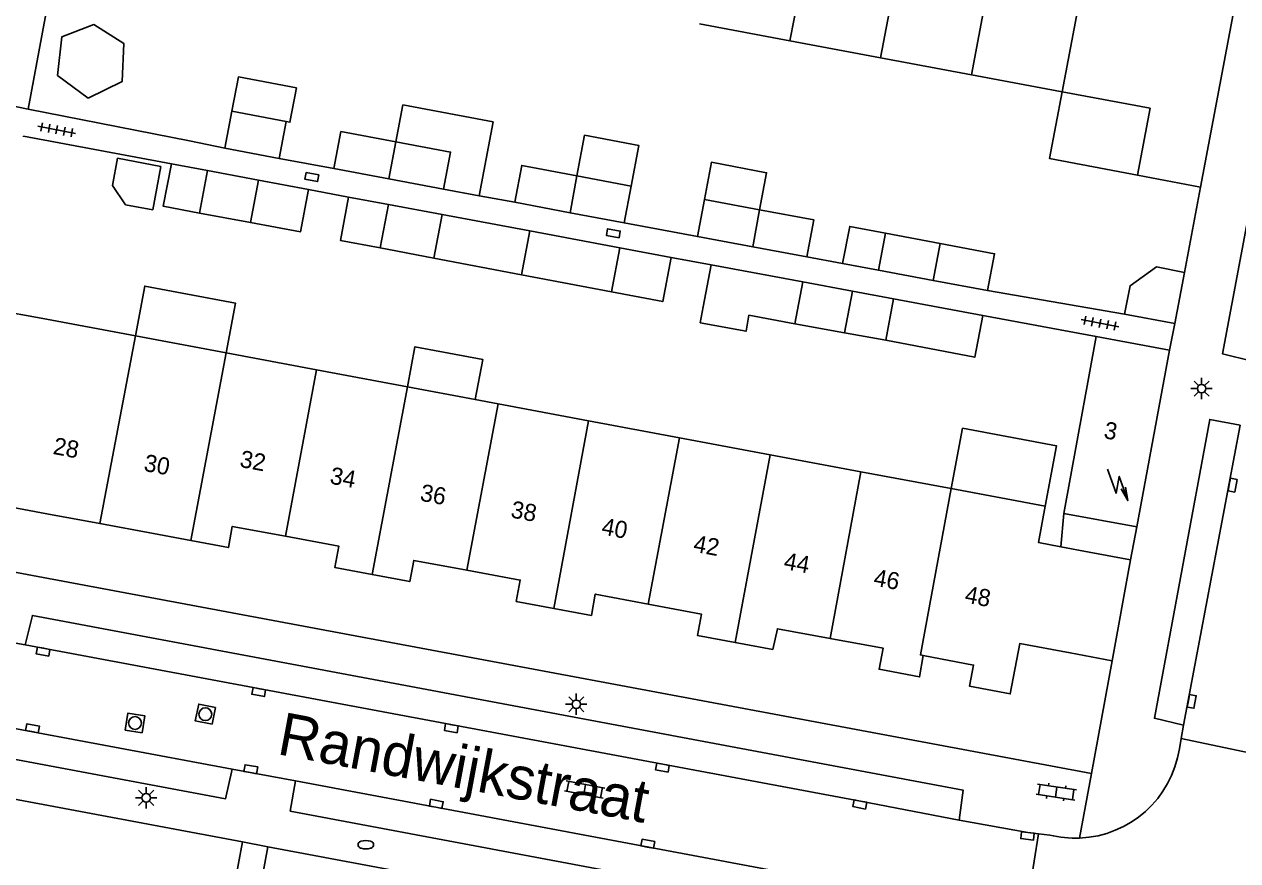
# Model space of a CAD drawing. Extents: x 124000 to 128010, y 398999 to 403000.
# Drawn here: x 126626.3 to 126697.3, y 399664.9 to 399713.9 of the extents above; entities that cross this region are included whole.
import ezdxf

# ---------------------------------------------------------------- set-up
doc = ezdxf.new("R2010")
doc.units = 0
for name, color, linetype in [('gg-afsc-erfafscheiding', 7, 'Continuous'), ('gg-afsc-muur', 7, 'Continuous'), ('gg-anno-huisnummerreeks BGT', 7, 'Continuous'), ('gg-anno-openbare ruimte label', 7, 'Continuous'), ('gg-bbg-bijgebouw', 7, 'Continuous'), ('gg-bbg-gedigitaliseerde bijgebouw', 7, 'Continuous'), ('gg-bbg-hoofdgebouw', 7, 'Continuous'), ('gg-bbg-luifel en loopbrug', 7, 'Continuous'), ('gg-bbg-tussenscheiding', 7, 'Continuous'), ('gg-knt-verharding', 7, 'Continuous'), ('gg-knt-verharding nz', 7, 'Continuous'), ('gt-grn-weggrens', 7, 'Continuous'), ('gt-symb-brandkraan', 7, 'Continuous'), ('gt-symb-klinker verharding', 7, 'Continuous'), ('gt-symb-kolk', 7, 'Continuous'), ('gt-symb-kolk center center', 7, 'Continuous'), ('gt-symb-lichtmast', 7, 'Continuous'), ('gt-symb-rioolschacht', 7, 'Continuous'), ('gt-symb-tegel verharding', 7, 'Continuous'), ('gt-symb-trafo symbool', 7, 'Continuous')]:
    doc.layers.add(name, color=color, linetype=linetype)

# ---------------------------------------------------------------- blocks, each defined once
blk = doc.blocks.new('gt0-LMAST')
at = {"layer": 'gt-symb-lichtmast'}
for p, q in [((-0.182, 0.173), (-0.447, 0.438)), ((-0.005, 0.246), (-0.005, 0.621)), ((0.172, 0.173), (0.437, 0.438)), ((-0.255, -0.004), (-0.63, -0.004)), ((-0.182, -0.181), (-0.447, -0.446)), ((-0.005, -0.254), (-0.005, -0.629)), ((0.437, -0.446), (0.172, -0.181)), ((0.245, -0.004), (0.62, -0.004))]:
    blk.add_line(p, q, dxfattribs=at)
blk.add_circle((-0.005, -0.004), 0.25, dxfattribs=at)
blk = doc.blocks.new('gt0-KOLK')
at = {"layer": 'gt-symb-kolk'}
blk.add_lwpolyline([(0, 0), (0.375, 0), (0.375, 0.4), (-0.375, 0.4), (-0.375, 0), (0, 0)], dxfattribs=at)
blk = doc.blocks.new('gt0-TEG1')
at = {"layer": 'gt-symb-tegel verharding'}
for p, q in [((-1.125, 0), (1.125, 0)), ((-0.9, -0.25), (-0.9, 0.25)), ((-0.45, -0.25), (-0.45, 0.25)), ((0, -0.25), (0, 0.25)), ((0.45, -0.25), (0.45, 0.25)), ((0.9, -0.25), (0.9, 0.25))]:
    blk.add_line(p, q, dxfattribs=at)
blk = doc.blocks.new('gt0-HSP')
at = {"layer": 'gt-symb-trafo symbool'}
for points in [[(0.771, 0.746), (-0.529, -0.004), (0.471, -0.004), (-0.829, -0.754)], [(-0.217, -0.24), (-0.829, -0.754), (-0.077, -0.48)]]:
    blk.add_lwpolyline(points, dxfattribs=at)
blk = doc.blocks.new('gt0-KL1')
at = {"layer": 'gt-symb-klinker verharding'}
for p, q in [((-1.15, 0.3), (1.15, 0.3)), ((-1, -0.3), (-1, 0.3)), ((-0.5, 0.3), (-0.5, 0.45)), ((0, -0.3), (0, 0.3)), ((0.5, 0.3), (0.5, 0.45)), ((1, -0.3), (1, 0.3)), ((-1.15, -0.3), (1.15, -0.3)), ((-0.5, -0.45), (-0.5, -0.3)), ((0.5, -0.45), (0.5, -0.3))]:
    blk.add_line(p, q, dxfattribs=at)
blk = doc.blocks.new('gt0-KOLKCC')
at = {"layer": 'gt-symb-kolk center center'}
blk.add_lwpolyline([(-0.375, 0.2), (0.375, 0.2), (0.375, -0.2), (-0.375, -0.2)], close=True, dxfattribs=at)
blk = doc.blocks.new('gt0-BR')
at = {"layer": 'gt-symb-brandkraan'}
for centre, radius, start, end in [((-0.244, 0), 0.206, 107.56694, 252.43307), ((0.599, -2.664), 3, 106.89205, 107.56694), ((0, -0.691), 0.938, 73.10799, 106.89205), ((-0.599, -2.664), 3, 72.43309, 73.10799), ((0.244, 0), 0.206, 287.56695, 72.43309), ((0.599, 2.664), 3, 252.43307, 253.10797), ((0, 0.691), 0.938, 253.10797, 286.89206), ((-0.599, 2.664), 3, 286.89206, 287.56695)]:
    blk.add_arc(centre, radius, start, end, dxfattribs=at)
blk = doc.blocks.new('gt0-RS')
at = {"layer": 'gt-symb-rioolschacht'}
blk.add_lwpolyline([(-0.5, -0.5), (0.5, -0.5), (0.5, 0.5), (-0.5, 0.5)], close=True, dxfattribs=at)
blk.add_circle((0, 0), 0.375, dxfattribs=at)

msp = doc.modelspace()

# ---------------------------------------------------------------- linework, layer by layer
at = {"layer": 'gg-afsc-erfafscheiding'}
for p, q in [((126644.385, 399705.421), (126641.192, 399706.016)), ((126642.904, 399704.195), (126645.241, 399703.758)), ((126654.976, 399703.446), (126652.89, 399703.835)), ((126665.666, 399701.453), (126661.384, 399702.239)), ((126664.132, 399700.225), (126666.47, 399699.788)), ((126674.168, 399699.868), (126672.079, 399700.257)), ((126690.669, 399696.893), (126682.654, 399698.281)), ((126689.014, 399695.59), (126682.364, 399696.815))]:
    msp.add_line(p, q, dxfattribs=at)
for points in [[(126626.495, 399708.888), (126627.958, 399716.771), (126628.884, 399718.452), (126629.145, 399718.635)], [(126626.495, 399708.888), (126635.926, 399707.054), (126638.005, 399706.61)]]:
    msp.add_lwpolyline(points, dxfattribs=at)
at = {"layer": 'gg-afsc-muur'}
msp.add_line((126695.113, 399704.337), (126694.183, 399699.35), dxfattribs=at)
msp.add_lwpolyline([(126634.872, 399705.697), (126626.223, 399707.315), (126626.217, 399707.284)], dxfattribs=at)
at = {"layer": 'gg-bbg-bijgebouw'}
for p, q in [((126641.192, 399706.016), (126638.005, 399706.61)), ((126647.611, 399704.819), (126644.385, 399705.421)), ((126636.983, 399705.302), (126639.968, 399704.744)), ((126639.968, 399704.744), (126642.904, 399704.195)), ((126650.804, 399704.224), (126647.611, 399704.819)), ((126647.577, 399703.321), (126650.727, 399702.732)), ((126658.209, 399702.837), (126654.976, 399703.446)), ((126650.727, 399702.732), (126655.855, 399701.773)), ((126661.384, 399702.239), (126658.209, 399702.837)), ((126655.855, 399701.773), (126661.129, 399700.787)), ((126665.666, 399701.453), (126668.9, 399700.85)), ((126661.129, 399700.787), (126664.132, 399700.225)), ((126668.9, 399700.85), (126672.079, 399700.257)), ((126666.47, 399699.788), (126671.827, 399698.786)), ((126679.475, 399698.876), (126676.257, 399699.479)), ((126693.613, 399696.35), (126694.183, 399699.35)), ((126671.827, 399698.786), (126674.737, 399698.242)), ((126682.654, 399698.281), (126679.475, 399698.876)), ((126677.145, 399697.791), (126682.364, 399696.815)), ((126693.613, 399696.35), (126690.669, 399696.893))]:
    msp.add_line(p, q, dxfattribs=at)
msp.add_lwpolyline([(126694.183, 399699.35), (126692.532, 399699.664), (126690.988, 399698.561), (126690.669, 399696.893)], dxfattribs=at)
at = {"layer": 'gg-bbg-gedigitaliseerde bijgebouw'}
for p, q in [((126638.005, 399706.61), (126638.417, 399708.779)), ((126638.417, 399708.779), (126641.602, 399708.175)), ((126641.602, 399708.175), (126641.192, 399706.016)), ((126634.26, 399705.551), (126631.718, 399706.026)), ((126636.983, 399705.302), (126636.522, 399702.821)), ((126658.616, 399704.999), (126661.794, 399704.401)), ((126661.794, 399704.401), (126661.384, 399702.239)), ((126647.094, 399700.78), (126647.577, 399703.321)), ((126666.075, 399703.61), (126665.666, 399701.453)), ((126669.307, 399703.007), (126666.075, 399703.61)), ((126639.499, 399702.268), (126636.522, 399702.821)), ((126676.668, 399701.643), (126676.257, 399699.479)), ((126679.885, 399701.038), (126676.668, 399701.643)), ((126650.243, 399700.182), (126647.094, 399700.78)), ((126655.368, 399699.209), (126650.243, 399700.182)), ((126666.47, 399699.788), (126666.006, 399697.341)), ((126660.64, 399698.207), (126655.368, 399699.209)), ((126674.274, 399695.804), (126674.737, 399698.242)), ((126676.686, 399695.377), (126677.145, 399697.791)), ((126671.363, 399696.345), (126668.685, 399696.843)), ((126671.363, 399696.345), (126674.274, 399695.804))]:
    msp.add_line(p, q, dxfattribs=at)
for points in [[(126648.018, 399706.984), (126644.795, 399707.588), (126644.385, 399705.421)], [(126648.018, 399706.984), (126651.214, 399706.385), (126650.804, 399704.224)], [(126631.718, 399706.026), (126631.419, 399704.428), (126632.186, 399703.308)], [(126634.26, 399705.551), (126633.785, 399703.009), (126632.186, 399703.308)], [(126658.616, 399704.999), (126655.386, 399705.605), (126654.976, 399703.446)], [(126639.499, 399702.268), (126642.435, 399701.722), (126642.904, 399704.195)], [(126669.307, 399703.007), (126672.488, 399702.414), (126672.079, 399700.257)], [(126679.885, 399701.038), (126683.065, 399700.44), (126682.654, 399698.281)], [(126660.64, 399698.207), (126663.641, 399697.637), (126664.132, 399700.225)], [(126668.685, 399696.843), (126668.51, 399695.902), (126665.831, 399696.4), (126666.006, 399697.341)], [(126682.364, 399696.815), (126681.902, 399694.386), (126676.686, 399695.377)]]:
    msp.add_lwpolyline(points, dxfattribs=at)
at = {"layer": 'gg-bbg-hoofdgebouw'}
for p, q in [((126665.787, 399713.884), (126671.085, 399712.893)), ((126697.032, 399714.462), (126695.855, 399708.257)), ((126671.085, 399712.893), (126676.392, 399711.9)), ((126676.392, 399711.9), (126681.71, 399710.904)), ((126681.71, 399710.904), (126687.018, 399709.911)), ((126687.018, 399709.911), (126692.159, 399708.949)), ((126692.159, 399708.949), (126691.418, 399705.036)), ((126695.855, 399708.257), (126695.113, 399704.337)), ((126691.418, 399705.036), (126695.113, 399704.337)), ((126624.29, 399697.206), (126627.249, 399696.666)), ((126627.249, 399696.666), (126632.771, 399695.633)), ((126632.771, 399695.633), (126638.079, 399694.639)), ((126687.112, 399685.248), (126689.014, 399695.59)), ((126689.014, 399695.59), (126693.29, 399694.795)), ((126693.29, 399694.795), (126691.388, 399684.453)), ((126638.079, 399694.639), (126643.377, 399693.648)), ((126643.377, 399693.648), (126648.694, 399692.653)), ((126648.694, 399692.653), (126652.658, 399691.911)), ((126652.658, 399691.911), (126654.002, 399691.659)), ((126654.002, 399691.659), (126659.3, 399690.668)), ((126659.3, 399690.668), (126664.618, 399689.672)), ((126664.618, 399689.672), (126669.926, 399688.679)), ((126669.926, 399688.679), (126675.233, 399687.686)), ((126675.233, 399687.686), (126680.522, 399686.696)), ((126680.522, 399686.696), (126686.026, 399685.666)), ((126627.59, 399685.227), (126630.693, 399684.65)), ((126691.388, 399684.453), (126687.112, 399685.248)), ((126630.693, 399684.65), (126633.819, 399684.068)), ((126633.819, 399684.068), (126636.014, 399683.658)), ((126686.939, 399683.29), (126688.596, 399682.98)), ((126691.023, 399682.529), (126688.596, 399682.98)), ((126689.939, 399676.622), (126691.023, 399682.529)), ((126687.489, 399677.083), (126689.939, 399676.622))]:
    msp.add_line(p, q, dxfattribs=at)
for points in [[(126622.793, 399689.164), (126625.727, 399688.577), (126625.209, 399685.669), (126627.59, 399685.227)], [(126686.026, 399685.666), (126685.637, 399683.534), (126686.939, 399683.29)], [(126636.014, 399683.658), (126638.211, 399683.247), (126638.44, 399684.483), (126641.557, 399683.907)], [(126641.557, 399683.907), (126644.675, 399683.33), (126644.441, 399682.082), (126646.635, 399681.671)], [(126646.635, 399681.671), (126648.829, 399681.259), (126649.061, 399682.497), (126652.178, 399681.92)], [(126652.178, 399681.92), (126655.297, 399681.342), (126655.063, 399680.094), (126657.259, 399679.683)], [(126657.259, 399679.683), (126659.458, 399679.271), (126659.682, 399680.523), (126662.791, 399679.94)], [(126662.791, 399679.94), (126665.903, 399679.356), (126665.669, 399678.108), (126667.873, 399677.694)], [(126667.873, 399677.694), (126670.075, 399677.281), (126670.351, 399678.497), (126673.441, 399677.928)], [(126673.441, 399677.928), (126676.53, 399677.359), (126676.298, 399676.121), (126678.666, 399675.677), (126678.879, 399676.93)], [(126678.879, 399676.93), (126681.829, 399676.37), (126681.596, 399675.132), (126683.982, 399674.683), (126684.531, 399677.624), (126687.489, 399677.083)]]:
    msp.add_lwpolyline(points, dxfattribs=at)
at = {"layer": 'gg-bbg-luifel en loopbrug'}
for p, q in [((126634.872, 399705.697), (126636.983, 399705.302)), ((126652.89, 399703.835), (126650.804, 399704.224)), ((126645.241, 399703.758), (126647.577, 399703.321)), ((126676.257, 399699.479), (126674.168, 399699.868)), ((126674.737, 399698.242), (126677.145, 399697.791)), ((126674.274, 399695.804), (126676.686, 399695.377))]:
    msp.add_line(p, q, dxfattribs=at)
for points in [[(126630, 399709.545), (126631.984, 399710.507), (126632.089, 399712.747), (126630.331, 399713.845), (126628.452, 399713.123), (126628.212, 399710.868), (126630, 399709.545)], [(126638.417, 399708.779), (126638.798, 399710.789), (126642.195, 399710.145), (126641.814, 399708.135), (126641.602, 399708.175)], [(126691.418, 399705.036), (126686.279, 399706.009), (126687.018, 399709.911)], [(126652.89, 399703.835), (126653.707, 399708.151), (126648.428, 399709.151), (126648.018, 399706.984)], [(126661.794, 399704.401), (126662.242, 399706.768), (126659.065, 399707.37), (126658.616, 399704.999)], [(126634.872, 399705.697), (126634.401, 399703.215), (126636.522, 399702.821)], [(126669.307, 399703.007), (126669.718, 399705.178), (126666.488, 399705.789), (126666.075, 399703.61)], [(126647.094, 399700.78), (126644.765, 399701.216), (126645.241, 399703.758)], [(126676.668, 399701.643), (126674.579, 399702.039), (126674.168, 399699.868)], [(126638.079, 399694.639), (126638.625, 399697.554), (126633.317, 399698.548), (126632.771, 399695.633)], [(126648.694, 399692.653), (126649.133, 399694.995), (126653.097, 399694.253), (126652.658, 399691.911)], [(126680.522, 399686.696), (126681.184, 399690.229), (126686.687, 399689.198), (126686.026, 399685.666)]]:
    msp.add_lwpolyline(points, dxfattribs=at)
at = {"layer": 'gg-bbg-tussenscheiding'}
for p, q in [((126672.963, 399722.746), (126671.085, 399712.893)), ((126678.26, 399721.752), (126676.392, 399711.9)), ((126683.557, 399720.758), (126681.71, 399710.904)), ((126688.874, 399719.76), (126687.018, 399709.911)), ((126647.611, 399704.819), (126648.018, 399706.984)), ((126639.499, 399702.268), (126639.968, 399704.744)), ((126658.209, 399702.837), (126658.616, 399704.999)), ((126650.727, 399702.732), (126650.243, 399700.182)), ((126668.9, 399700.85), (126669.307, 399703.007)), ((126655.855, 399701.773), (126655.368, 399699.209)), ((126661.129, 399700.787), (126660.64, 399698.207)), ((126679.475, 399698.876), (126679.885, 399701.038)), ((126671.827, 399698.786), (126671.363, 399696.345)), ((126630.693, 399684.65), (126632.771, 399695.633)), ((126636.014, 399683.658), (126638.079, 399694.639)), ((126641.557, 399683.907), (126643.377, 399693.648)), ((126646.635, 399681.671), (126648.694, 399692.653)), ((126652.178, 399681.92), (126654.002, 399691.659)), ((126657.259, 399679.683), (126659.3, 399690.668)), ((126662.791, 399679.94), (126664.618, 399689.672)), ((126667.873, 399677.694), (126669.926, 399688.679)), ((126673.441, 399677.928), (126675.233, 399687.686))]:
    msp.add_line(p, q, dxfattribs=at)
msp.add_lwpolyline([(126680.522, 399686.696), (126678.722, 399676.96), (126678.879, 399676.93)], dxfattribs=at)
at = {"layer": 'gg-knt-verharding'}
for p, q in [((126626.495, 399708.888), (126625.068, 399709.196)), ((126693.29, 399694.795), (126693.613, 399696.35)), ((126687.112, 399685.248), (126686.939, 399683.29)), ((126688.729, 399670.019), (126621.579, 399682.565)), ((126626.308, 399677.546), (126625.558, 399677.687)), ((126582.611, 399676.583), (126639.035, 399666.022)), ((126689.939, 399676.622), (126688.729, 399670.019)), ((126694.126, 399672.849), (126693.985, 399672.074)), ((126693.985, 399672.074), (126698.7, 399671.078)), ((126642.133, 399669.588), (126638.426, 399670.272)), ((126684.854, 399661.572), (126685.641, 399666.498)), ((126638.338, 399662.303), (126639.035, 399666.022)), ((126639.035, 399666.022), (126640.525, 399665.743)), ((126639.831, 399662.04), (126640.525, 399665.743)), ((126640.525, 399665.743), (126686.366, 399657.163))]:
    msp.add_line(p, q, dxfattribs=at)
for points in [[(126699.681, 399712.014), (126696.407, 399694.575), (126698.147, 399694.147)], [(126697.444, 399690.41), (126695.66, 399690.747), (126692.414, 399673.259), (126694.126, 399672.849)], [(126588.324, 399679.668), (126588.072, 399677.901), (126638.044, 399668.55), (126638.426, 399670.272)], [(126680.99, 399667.297), (126681.23, 399669.047), (126626.744, 399679.28), (126626.308, 399677.546)], [(126680.15, 399662.423), (126679.755, 399660.711), (126641.836, 399667.83), (126642.133, 399669.588)], [(126685.641, 399666.498), (126685.013, 399666.569), (126680.99, 399667.297)]]:
    msp.add_lwpolyline(points, dxfattribs=at)
at = {"layer": 'gg-knt-verharding nz'}
for p, q in [((126697.444, 399690.41), (126694.126, 399672.849)), ((126624.643, 399672.857), (126638.426, 399670.272)), ((126693.985, 399672.074), (126693.876, 399671.471)), ((126685.641, 399666.498), (126686.289, 399666.425))]:
    msp.add_line(p, q, dxfattribs=at)
for points in [[(126680.99, 399667.297), (126675.208, 399668.41), (126626.308, 399677.546)], [(126642.133, 399669.588), (126674.344, 399663.55), (126680.15, 399662.423)]]:
    msp.add_lwpolyline(points, dxfattribs=at)
for centre, radius, start, end in [((126687.783, 399672.405), 6.165, 272.35488, 351.28259), ((126687.786, 399672.417), 6.176, 255.97655, 272.32308)]:
    msp.add_arc(centre, radius, start, end, dxfattribs=at)
at = {"layer": 'gt-grn-weggrens'}
for p, q in [((126691.023, 399682.529), (126691.388, 399684.453)), ((126688.036, 399666.246), (126688.729, 399670.019))]:
    msp.add_line(p, q, dxfattribs=at)

# ---------------------------------------------------------------- block references
at = {"layer": 'gt-symb-brandkraan'}
msp.add_blockref('gt0-BR', (126646.256, 399665.857), dxfattribs=at)
at = {"layer": 'gt-symb-klinker verharding'}
for p, rotation in [((126659.066, 399669.088), 169.39794170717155), ((126686.667, 399668.938), -8.45426172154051)]:
    msp.add_blockref('gt0-KL1', p, dxfattribs=dict(at, rotation=rotation))
at = {"layer": 'gt-symb-kolk'}
for p, rotation in [((126696.798, 399686.93), -100.54573436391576), ((126627.398, 399677.353), 169.39794170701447), ((126640.023, 399674.985), 169.39794170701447), ((126694.407, 399674.284), -100.71464389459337), ((126626.708, 399672.476), -10.714643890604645), ((126651.298, 399672.875), 169.39794170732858), ((126639.486, 399670.08), -10.25359802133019), ((126663.651, 399670.567), 169.4542656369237), ((126650.345, 399668.052), -10.602058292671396), ((126675.208, 399668.41), 169.10581701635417), ((126685.013, 399666.569), 173.57125225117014), ((126662.723, 399665.72), -10.658361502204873)]:
    msp.add_blockref('gt0-KOLK', p, dxfattribs=dict(at, rotation=rotation))
at = {"layer": 'gt-symb-kolk center center'}
for p, rotation in [((126643.099, 399704.925), -10.558187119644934), ((126660.744, 399701.636), 169.44181287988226)]:
    msp.add_blockref('gt0-KOLKCC', p, dxfattribs=dict(at, rotation=rotation))
at = {"layer": 'gt-symb-lichtmast'}
for p in [(126695.186, 399692.548), (126658.582, 399674.078), (126633.4, 399668.603)]:
    msp.add_blockref('gt0-LMAST', p, dxfattribs=at)
at = {"layer": 'gt-symb-rioolschacht'}
for p, rotation in [((126636.865, 399673.495), 78.52151796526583), ((126632.745, 399672.982), 81.54573827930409)]:
    msp.add_blockref('gt0-RS', p, dxfattribs=dict(at, rotation=rotation))
at = {"layer": 'gt-symb-tegel verharding', "rotation": -10.781616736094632}
for p in [(126628.163, 399707.692), (126689.231, 399696.371)]:
    msp.add_blockref('gt0-TEG1', p, dxfattribs=at)
at = {"layer": 'gt-symb-trafo symbool', "rotation": 79.57734546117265}
msp.add_blockref('gt0-HSP', (126690.265, 399686.943), dxfattribs=at)

# ---------------------------------------------------------------- texts
at = {"layer": 'gg-anno-huisnummerreeks BGT'}
for s, rotation, p in [('3', 349.6, (126689.408, 399689.654)), ('28', 349.5, (126627.897, 399688.729)), ('30', 349.5, (126633.215, 399687.74)), ('32', 349.5, (126638.829, 399687.971)), ('34', 349.5, (126644.105, 399686.995)), ('36', 349.5, (126649.387, 399685.996)), ('38', 349.5, (126654.691, 399685.014)), ('40', 349.4, (126660.006, 399684.024)), ('42', 349.4, (126665.38, 399683.015)), ('44', 349.6, (126670.673, 399681.996)), ('46', 349.6, (126675.931, 399681.027)), ('48', 349.3, (126681.267, 399680.039))]:
    msp.add_text(s, height=1, rotation=rotation, dxfattribs=at).set_placement(p)
at = {"layer": 'gg-anno-openbare ruimte label'}
msp.add_text('Randwijkstraat', height=2.5, rotation=349.4, dxfattribs=at).set_placement((126640.999, 399671.17))

doc.saveas('drawing.dxf')
